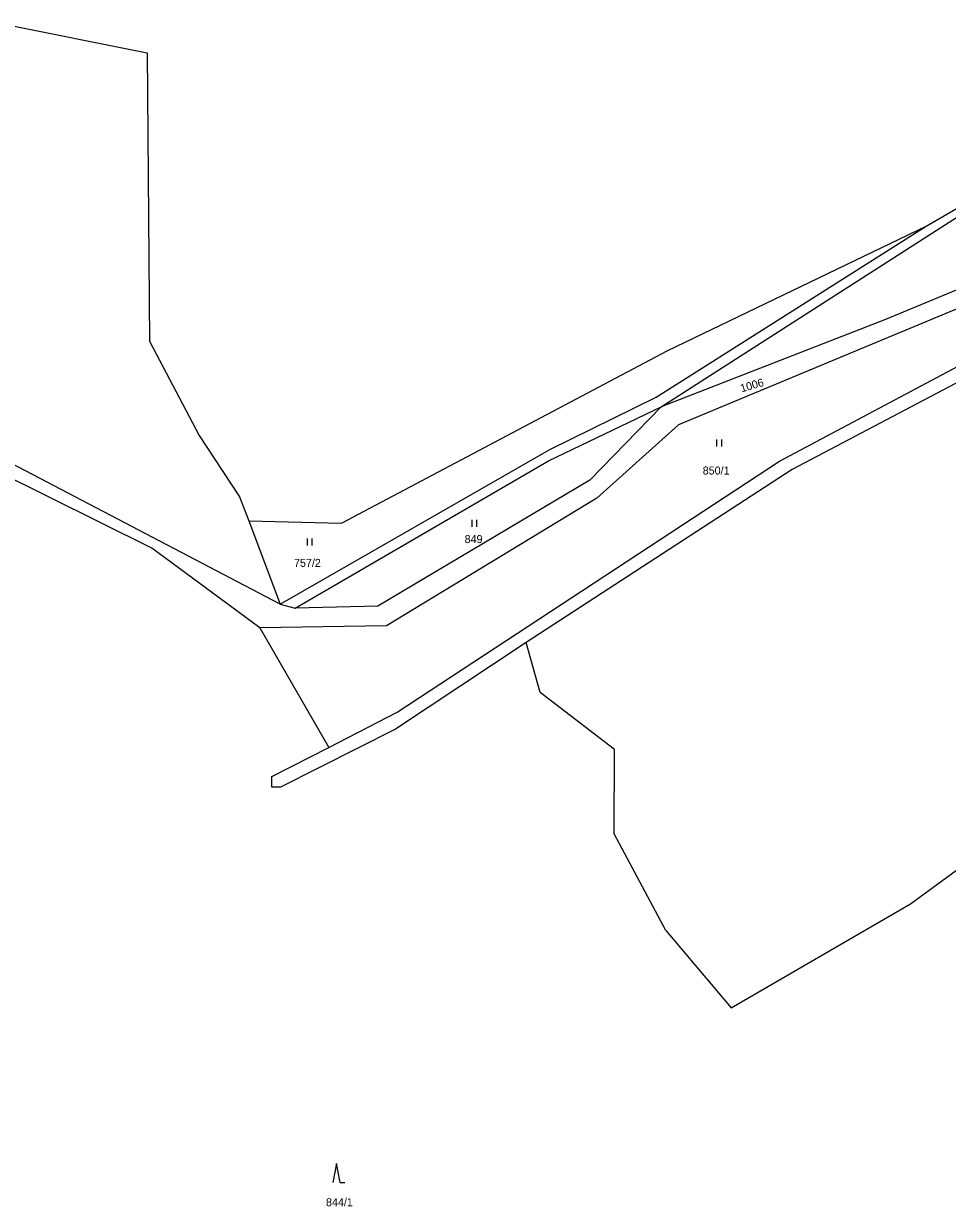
# Model space of a CAD drawing. Extents: x -744132 to -742433, y -984679 to -982287.
# Drawn here: x -743636.5 to -743440.4, y -982952 to -982700.8 of the extents above; entities that cross this region are included whole.
import ezdxf

# ---------------------------------------------------------------- set-up
doc = ezdxf.new("R2010")
doc.units = 0
doc.header["$LTSCALE"] = 0.68
doc.layers.add('1', color=7, linetype='Continuous', lineweight=25)
doc.layers.add('3', color=7, linetype='Continuous', lineweight=25)
doc.layers.add('2', color=7, linetype='Continuous')

msp = doc.modelspace()

# ---------------------------------------------------------------- linework, layer by layer
at = {"layer": '1'}
for p, q in [((-743641.35, -982700.84), (-743610.26, -982707.04)), ((-743610.26, -982707.04), (-743609.77, -982768.24)), ((-743444.9, -982743.86), (-743434.31, -982737.66)), ((-743501.13, -982782.2), (-743437.23, -982741.22)), ((-743502.21, -982780.17), (-743444.9, -982743.86)), ((-743499.88, -982770.28), (-743444.9, -982743.86)), ((-743409.47, -982745.36), (-743453.51, -982763.67)), ((-743410.39, -982749.69), (-743497.45, -982786.05)), ((-743475.99, -982793.71), (-743401.62, -982754.22)), ((-743403.06, -982758.47), (-743473.35, -982795.48)), ((-743453.51, -982763.67), (-743501.13, -982782.2)), ((-743609.77, -982768.24), (-743599.21, -982788.27)), ((-743569, -982806.91), (-743499.88, -982770.28)), ((-743582.04, -982824.08), (-743670.68, -982777.75)), ((-743524.81, -982791.24), (-743502.21, -982780.17)), ((-743525.08, -982793.69), (-743501.13, -982782.2)), ((-743501.13, -982782.2), (-743516.27, -982797.74)), ((-743497.45, -982786.05), (-743514.8, -982801.58)), ((-743599.21, -982788.27), (-743590.68, -982801.3)), ((-743609.33, -982812.2), (-743654.75, -982789.61)), ((-743582.04, -982824.08), (-743524.81, -982791.24)), ((-743578.86, -982824.96), (-743525.08, -982793.69)), ((-743557.18, -982847.07), (-743475.99, -982793.71)), ((-743473.35, -982795.48), (-743529.79, -982832.25)), ((-743516.27, -982797.74), (-743561.33, -982824.54)), ((-743590.68, -982801.3), (-743588.67, -982806.4)), ((-743514.8, -982801.58), (-743559.49, -982828.74)), ((-743588.67, -982806.4), (-743569, -982806.91)), ((-743588.67, -982806.4), (-743582.04, -982824.08)), ((-743586.33, -982829.11), (-743609.33, -982812.2)), ((-743582.04, -982824.08), (-743578.86, -982824.96)), ((-743561.33, -982824.54), (-743578.86, -982824.96)), ((-743559.49, -982828.74), (-743586.33, -982829.11)), ((-743586.33, -982829.11), (-743571.73, -982854.54)), ((-743529.79, -982832.25), (-743557.56, -982850.62)), ((-743526.85, -982842.84), (-743529.79, -982832.25)), ((-743511.06, -982854.95), (-743526.85, -982842.84)), ((-743571.73, -982854.54), (-743557.18, -982847.07)), ((-743557.56, -982850.62), (-743581.96, -982862.96)), ((-743583.78, -982860.73), (-743571.73, -982854.54)), ((-743511.1, -982872.87), (-743511.06, -982854.95)), ((-743583.82, -982862.96), (-743583.78, -982860.73)), ((-743581.96, -982862.96), (-743583.82, -982862.96)), ((-743448.22, -982887.75), (-743420.89, -982867.75)), ((-743500.12, -982893.41), (-743511.1, -982872.87)), ((-743486.26, -982909.79), (-743448.22, -982887.75)), ((-743500.12, -982893.41), (-743486.26, -982909.79))]:
    msp.add_line(p, q, dxfattribs=at)
at = {"layer": '3'}
for p, q in [((-743489.291, -982790.64), (-743489.291, -982789.14)), ((-743488.29, -982790.64), (-743488.29, -982789.14)), ((-743541.261, -982807.67), (-743541.261, -982806.17)), ((-743540.26, -982807.67), (-743540.26, -982806.17)), ((-743576.261, -982811.64), (-743576.261, -982810.14)), ((-743575.26, -982811.64), (-743575.26, -982810.14)), ((-743569.34, -982946.88), (-743568.344, -982946.88))]:
    msp.add_line(p, q, dxfattribs=at)
msp.add_lwpolyline([(-743569.34, -982946.88), (-743570.09, -982942.88), (-743570.84, -982946.88)], dxfattribs=at)

# ---------------------------------------------------------------- texts
at = {"layer": '2'}
msp.add_text('1006', height=1.7, rotation=16, dxfattribs=at).set_placement((-743484.062, -982779.138))
for s, p in [('850/1', (-743492.32, -982796.575)), ('849', (-743542.88, -982811.135)), ('757/2', (-743579.1, -982816.185)), ('844/1', (-743572.31, -982951.945))]:
    msp.add_text(s, height=1.7, dxfattribs=at).set_placement(p)

doc.saveas('drawing.dxf')
